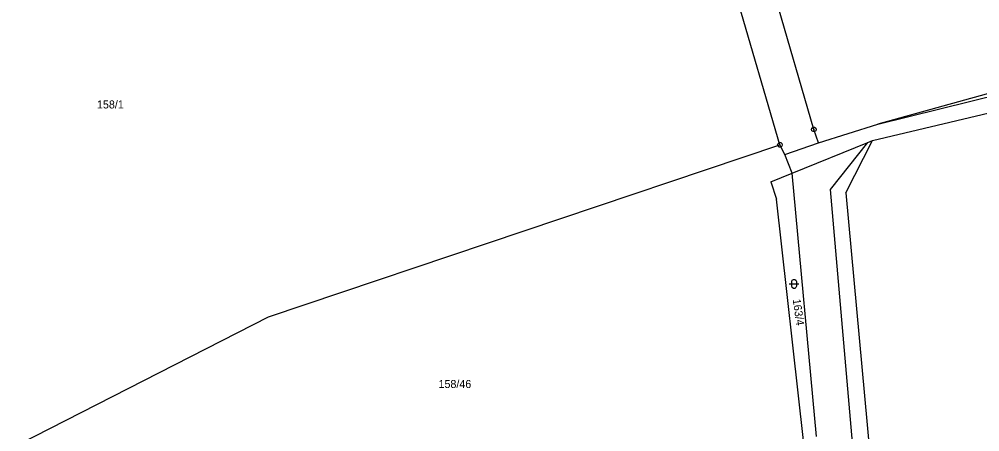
# Model space of a CAD drawing. Extents: x -780000 to -777378, y -1011169 to -1009297.
# Drawn here: x -779410.4 to -779206.4, y -1009967.9 to -1009880.5 of the extents above; entities that cross this region are included whole.
import ezdxf

# ---------------------------------------------------------------- set-up
doc = ezdxf.new("R2010")
doc.units = 0
for name, color, linetype in [('Default', 7, 'Continuous'), ('KN_HRANICE', 7, 'Continuous'), ('KN_KULTURY', 7, 'Continuous'), ('KN_PARCELY', 7, 'Continuous')]:
    doc.layers.add(name, color=color, linetype=linetype)

# ---------------------------------------------------------------- blocks, each defined once
blk = doc.blocks.new('316')
at = {"layer": 'Default'}
for points in [[(-1, 1), (0.27, 1), (1, 1)], [(-0.5, 1.5), (-0.4, 1.79), (-0.15, 1.97), (0.16, 1.97), (0.41, 1.79), (0.51, 1.5), (0.51, 0.5), (0.41, 0.21), (0.16, 0.03), (-0.15, 0.03), (-0.4, 0.21), (-0.5, 0.5), (-0.5, 1.5)]]:
    blk.add_lwpolyline(points, dxfattribs=at)
blk = doc.blocks.new('105')
at = {"layer": 'Default'}
blk.add_line((-0.12, 0), (0.12, 0), dxfattribs=at)
blk.add_lwpolyline([(0.15, 0.48), (0.4, 0.3), (0.5, 0.01), (0.4, -0.28), (0.15, -0.46), (-0.16, -0.46), (-0.41, -0.28), (-0.51, 0.01), (-0.41, 0.3), (-0.16, 0.48), (0.15, 0.48)], dxfattribs=at)

msp = doc.modelspace()

# ---------------------------------------------------------------- linework, layer by layer
at = {"layer": 'KN_HRANICE'}
for p, q in [((-779241.62, -1009903.83), (-779272.7, -1009797.05)), ((-779248.82, -1009907.09), (-779278.74, -1009805.06)), ((-779161.05, -1009884.21), (-779228.01, -1009902.71)), ((-779228.01, -1009902.71), (-779160.94, -1009886.18)), ((-779229.16, -1009906.17), (-779157.23, -1009889.11)), ((-779240.66, -1009906.64), (-779228.01, -1009902.71)), ((-779240.66, -1009906.64), (-779241.62, -1009903.83)), ((-779247.8, -1009909.13), (-779240.66, -1009906.64)), ((-779246.23, -1009913.12), (-779230.18, -1009906.58)), ((-779238.1, -1009916.55), (-779230.18, -1009906.58)), ((-779234.8, -1009917.25), (-779229.16, -1009906.17)), ((-779230.18, -1009906.58), (-779229.16, -1009906.17)), ((-779357.43, -1009943.56), (-779248.82, -1009907.09)), ((-779247.8, -1009909.13), (-779248.82, -1009907.09)), ((-779246.23, -1009913.12), (-779247.8, -1009909.13)), ((-779250.74, -1009914.96), (-779246.23, -1009913.12)), ((-779250.74, -1009914.96), (-779249.52, -1009918.58)), ((-779241.08, -1009968.91), (-779246.23, -1009913.12)), ((-779233.71, -1009966.95), (-779238.1, -1009916.55)), ((-779243.85, -1009969.77), (-779249.52, -1009918.58)), ((-779234.8, -1009917.25), (-779223.59, -1010039.03)), ((-779410.38, -1009970.58), (-779357.43, -1009943.56)), ((-779226.79, -1010039.25), (-779233.71, -1009966.95))]:
    msp.add_line(p, q, dxfattribs=at)

# ---------------------------------------------------------------- block references
at = {"layer": 'KN_KULTURY'}
msp.add_blockref('316', (-779245.83, -1009937.58), dxfattribs=at)
at = {"layer": 'KN_PARCELY'}
for p in [(-779241.62, -1009903.83), (-779248.82, -1009907.09)]:
    msp.add_blockref('105', p, dxfattribs=at)

# ---------------------------------------------------------------- texts
for s, p in [('158/1', (-779393.86, -1009899.38)), ('158/46', (-779321.33, -1009958.65))]:
    msp.add_text(s, height=1.7, dxfattribs=at).set_placement(p)
msp.add_text('163/4', height=1.7, rotation=277.999, dxfattribs=at).set_placement((-779246.12, -1009939.86))

doc.saveas('drawing.dxf')
